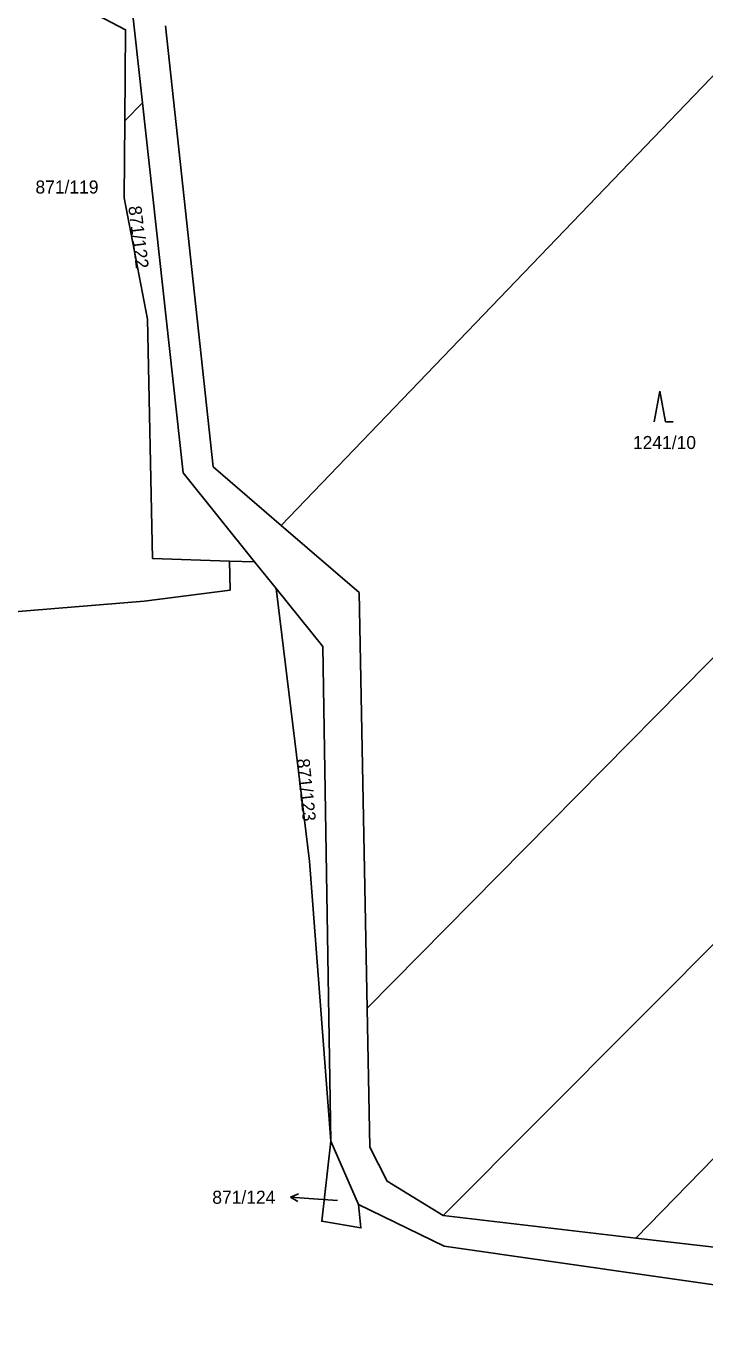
# Model space of a CAD drawing. Extents: x -776734 to -748832, y -1118122 to -976986.
# Drawn here: x -752501.9 to -752413.4, y -1114822 to -1114652.2 of the extents above; entities that cross this region are included whole.
import ezdxf

# ---------------------------------------------------------------- set-up
doc = ezdxf.new("R2010")
doc.units = 0
for name, color, linetype in [('KM_Hranice obce', 7, 'Continuous'), ('KM_Hranice parcel', 7, 'Continuous'), ('KM_Parcelní čísla', 7, 'Continuous'), ('KM_Pop  PČ popisy', 7, 'Continuous'), ('KM_Značky kultur', 7, 'Continuous')]:
    doc.layers.add(name, color=color, linetype=linetype)

msp = doc.modelspace()

# ---------------------------------------------------------------- linework, layer by layer
at = {"layer": 'KM_Hranice obce'}
for p, q in [((-752483.72, -1114652.2), (-752477.54, -1114709.69)), ((-752483.72, -1114652.2), (-752477.54, -1114709.69)), ((-752477.54, -1114709.69), (-752468.64, -1114717.34)), ((-752477.54, -1114709.69), (-752468.64, -1114717.34)), ((-752468.64, -1114717.34), (-752458.5, -1114726.06)), ((-752468.64, -1114717.34), (-752458.5, -1114726.06)), ((-752458.5, -1114726.06), (-752457.45, -1114780.24)), ((-752458.5, -1114726.06), (-752457.45, -1114780.24)), ((-752422.42, -1114810.19), (-752447.56, -1114807.26)), ((-752422.42, -1114810.19), (-752447.56, -1114807.26)), ((-752422.42, -1114810.19), (-752407.34, -1114811.95)), ((-752422.42, -1114810.19), (-752407.34, -1114811.95))]:
    msp.add_line(p, q, dxfattribs=at)
msp.add_lwpolyline([(-752457.45, -1114780.24), (-752457.1, -1114798.36), (-752454.84, -1114802.78), (-752447.56, -1114807.26)], dxfattribs=at)
msp.add_lwpolyline([(-752457.45, -1114780.24), (-752457.1, -1114798.36), (-752454.84, -1114802.78), (-752447.56, -1114807.26)], dxfattribs=at)
at = {"layer": 'KM_Hranice parcel'}
for p, q in [((-752490.71, -1114625.87), (-752486.73, -1114662.25)), ((-752401, -1114646.87), (-752468.64, -1114717.34)), ((-752489.03, -1114664.6), (-752486.73, -1114662.25)), ((-752457.45, -1114780.24), (-752363.39, -1114684.92)), ((-752447.56, -1114807.26), (-752345.18, -1114704.46)), ((-752472.14, -1114722.04), (-752475.41, -1114721.99)), ((-752469.33, -1114725.54), (-752472.14, -1114722.04)), ((-752462.17, -1114797.56), (-752458.58, -1114805.8))]:
    msp.add_line(p, q, dxfattribs=at)
for points in [[(-752236.62, -1114619.65), (-752328.86, -1114714.25), (-752422.42, -1114810.19)], [(-752489.03, -1114664.6), (-752488.94, -1114652.72), (-752494.5, -1114649.8), (-752492.21, -1114627.15)], [(-752486.73, -1114662.25), (-752481.45, -1114710.47), (-752472.14, -1114722.04)], [(-752475.41, -1114721.99), (-752485.44, -1114721.61), (-752486.09, -1114690.45), (-752489.11, -1114674.61), (-752489.03, -1114664.6)], [(-752475.41, -1114721.99), (-752475.32, -1114725.74), (-752486.5, -1114727.2), (-752504.48, -1114728.64)], [(-752462.17, -1114797.56), (-752464.95, -1114761.08), (-752469.33, -1114725.54)], [(-752469.33, -1114725.54), (-752463.24, -1114733.1), (-752462.17, -1114797.56)], [(-752458.58, -1114805.8), (-752458.27, -1114808.86), (-752463.36, -1114808), (-752462.17, -1114797.56)], [(-752294.14, -1114897.88), (-752303.09, -1114881.16), (-752331.63, -1114845.67), (-752342.48, -1114833.24), (-752377.1, -1114821.34), (-752447.41, -1114811.26), (-752458.58, -1114805.8)]]:
    msp.add_lwpolyline(points, dxfattribs=at)
at = {"layer": 'KM_Pop  PČ popisy'}
for p, q in [((-752467.444, -1114804.871), (-752466.41, -1114804.441)), ((-752464.45, -1114805.08), (-752467.444, -1114804.871)), ((-752467.444, -1114804.871), (-752466.48, -1114805.44)), ((-752461.32, -1114805.3), (-752464.45, -1114805.08))]:
    msp.add_line(p, q, dxfattribs=at)
at = {"layer": 'KM_Značky kultur'}
for p, q in [((-752419.3, -1114699.81), (-752420.05, -1114703.81)), ((-752418.55, -1114703.81), (-752419.3, -1114699.81)), ((-752418.55, -1114703.81), (-752417.554, -1114703.81))]:
    msp.add_line(p, q, dxfattribs=at)

# ---------------------------------------------------------------- texts
at = {"layer": 'KM_Parcelní čísla'}
for s, p in [('871/119', (-752500.68, -1114674.06)), ('1241/10', (-752422.81, -1114707.36)), ('871/124', (-752477.633, -1114805.72))]:
    msp.add_text(s, height=1.7, dxfattribs=at).set_placement(p)
for s, rotation, p in [('871/122', 277, (-752488.583, -1114675.763)), ('871/123', 275.999997, (-752466.665, -1114747.778))]:
    msp.add_text(s, height=1.7, rotation=rotation, dxfattribs=at).set_placement(p)

doc.saveas('drawing.dxf')
